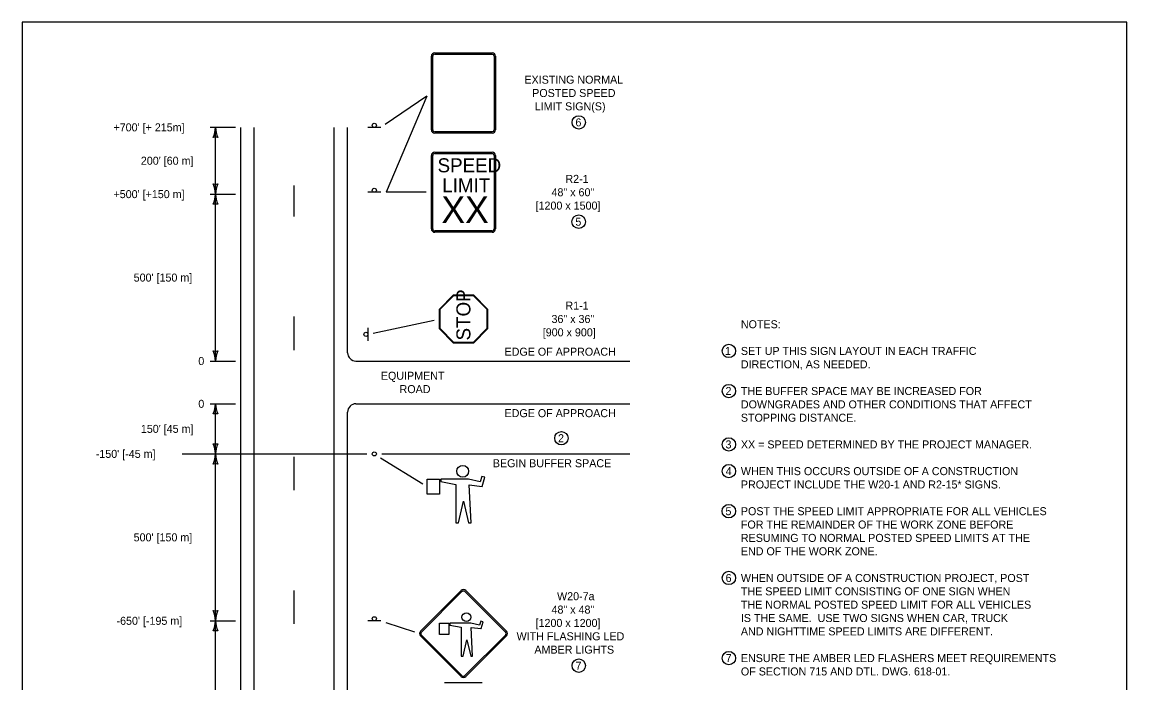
# Model space of a CAD drawing. Extents: x 49991.4 to 50021, y 49987.6 to 50011.4.
# Drawn here: x 50000.34 to 50008.61, y 50006.31 to 50011.26 of the extents above; entities that cross this region are included whole.
import ezdxf

# ---------------------------------------------------------------- set-up
doc = ezdxf.new("R2010")
doc.units = 0
for name, color, linetype in [('Level 1', 7, 'Continuous'), ('Level 2', 7, 'Continuous'), ('Level 3', 7, 'Continuous')]:
    doc.layers.add(name, color=color, linetype=linetype)

msp = doc.modelspace()

# ---------------------------------------------------------------- linework, layer by layer
at = {"layer": 'Level 1'}
for p, q in [((50003.4027, 50010.4569), (50003.4027, 50011.0069)), ((50003.4127, 50010.4569), (50003.4127, 50011.0069)), ((50003.4277, 50011.0319), (50003.8577, 50011.0319)), ((50003.4277, 50011.0219), (50003.8577, 50011.0219)), ((50003.8727, 50011.0069), (50003.8727, 50010.4569)), ((50003.8827, 50011.0069), (50003.8827, 50010.4569)), ((50001.9751, 50003.2038), (50001.9751, 50010.4747)), ((50002.0751, 50003.2038), (50002.0751, 50010.4747)), ((50002.6751, 50003.2038), (50002.6751, 50010.4747)), ((50002.775, 50008.7872), (50002.775, 50010.4747)), ((50003.023, 50010.4747), (50002.927, 50010.4747)), ((50003.8577, 50010.4419), (50003.4277, 50010.4419)), ((50003.8577, 50010.4319), (50003.4277, 50010.4319)), ((50003.4027, 50009.7137), (50003.4027, 50010.2637)), ((50003.4127, 50009.7137), (50003.4127, 50010.2637)), ((50003.4277, 50010.2887), (50003.8577, 50010.2887)), ((50003.4277, 50010.2787), (50003.8577, 50010.2787)), ((50003.8727, 50010.2637), (50003.8727, 50009.7137)), ((50003.8827, 50010.2637), (50003.8827, 50009.7137)), ((50002.375, 50009.8074), (50002.375, 50010.0394)), ((50003.023, 50009.9887), (50002.927, 50009.9887)), ((50003.8577, 50009.6987), (50003.4277, 50009.6987)), ((50003.8577, 50009.6887), (50003.4277, 50009.6887)), ((50002.375, 50008.8074), (50002.375, 50009.0574)), ((50002.927, 50008.9727), (50002.927, 50008.8767)), ((50002.8375, 50008.7247), (50004.89, 50008.7247)), ((50002.8375, 50008.4045), (50004.89, 50008.4045)), ((50002.7751, 50003.2038), (50002.7751, 50008.342)), ((50002.375, 50007.7574), (50002.375, 50008.0074)), ((50003.372, 50007.7285), (50003.372, 50007.841)), ((50003.372, 50007.841), (50003.4639, 50007.841)), ((50003.4639, 50007.841), (50003.4639, 50007.7285)), ((50003.6811, 50007.8403), (50003.4742, 50007.8403)), ((50003.4742, 50007.8403), (50003.4742, 50007.8217)), ((50003.4742, 50007.8217), (50003.5867, 50007.7995)), ((50003.7679, 50007.8203), (50003.6811, 50007.8403)), ((50003.7806, 50007.8599), (50003.7679, 50007.8203)), ((50003.8026, 50007.8544), (50003.7806, 50007.8599)), ((50003.7826, 50007.7856), (50003.8026, 50007.8544)), ((50003.4639, 50007.7285), (50003.372, 50007.7285)), ((50003.5867, 50007.7995), (50003.5867, 50007.5132)), ((50003.6998, 50007.5132), (50003.685, 50007.7966)), ((50003.685, 50007.7966), (50003.7826, 50007.7856)), ((50003.6049, 50007.5132), (50003.6432, 50007.6745)), ((50003.6432, 50007.6745), (50003.6815, 50007.5132)), ((50003.5867, 50007.5132), (50003.6049, 50007.5132)), ((50003.6815, 50007.5132), (50003.6998, 50007.5132)), ((50002.375, 50006.7574), (50002.375, 50007.0074)), ((50003.6249, 50007.0053), (50003.3208, 50006.7013)), ((50003.6319, 50006.9983), (50003.3279, 50006.6942)), ((50003.9572, 50006.6942), (50003.6532, 50006.9983)), ((50003.9643, 50006.7013), (50003.6602, 50007.0053)), ((50003.023, 50006.7795), (50002.927, 50006.7795)), ((50003.4642, 50006.6776), (50003.4642, 50006.7626)), ((50003.4642, 50006.7626), (50003.5337, 50006.7626)), ((50003.5337, 50006.7626), (50003.5337, 50006.6776)), ((50003.698, 50006.7622), (50003.5415, 50006.7622)), ((50003.5415, 50006.7622), (50003.5415, 50006.7481)), ((50003.5415, 50006.7481), (50003.6265, 50006.7313)), ((50003.7636, 50006.747), (50003.698, 50006.7622)), ((50003.7732, 50006.777), (50003.7636, 50006.747)), ((50003.7898, 50006.7728), (50003.7732, 50006.777)), ((50003.7747, 50006.7208), (50003.7898, 50006.7728)), ((50003.3208, 50006.6659), (50003.6249, 50006.3619)), ((50003.3279, 50006.673), (50003.6319, 50006.3689)), ((50003.5337, 50006.6776), (50003.4642, 50006.6776)), ((50003.6265, 50006.7313), (50003.6265, 50006.5148)), ((50003.6532, 50006.3689), (50003.9572, 50006.673)), ((50003.6602, 50006.3619), (50003.9643, 50006.6659)), ((50003.712, 50006.5148), (50003.7008, 50006.7291)), ((50003.7008, 50006.7291), (50003.7747, 50006.7208)), ((50003.6403, 50006.5148), (50003.6692, 50006.6368)), ((50003.6692, 50006.6368), (50003.6982, 50006.5148)), ((50003.6265, 50006.5148), (50003.6403, 50006.5148)), ((50003.6982, 50006.5148), (50003.712, 50006.5148)), ((50003.7839, 50006.3146), (50003.5016, 50006.3146))]:
    msp.add_line(p, q, dxfattribs=at)
for points in [[(50008.6146, 50011.2628), (50000.3356, 50011.2628), (50000.3356, 50000.0624), (50008.6146, 50000.0624)], [(50003.4627, 50008.9651), (50003.4627, 50009.1143), (50003.5682, 50009.2197), (50003.7172, 50009.2197), (50003.8227, 50009.1143), (50003.8227, 50008.9651), (50003.7172, 50008.8597), (50003.5682, 50008.8597)], [(50003.4677, 50008.9672), (50003.4677, 50009.1122), (50003.5702, 50009.2147), (50003.7152, 50009.2147), (50003.8177, 50009.1122), (50003.8177, 50008.9672), (50003.7152, 50008.8647), (50003.5702, 50008.8647)]]:
    msp.add_lwpolyline(points, close=True, dxfattribs=at)
for points in [[(50003.7805, 50007.8597), (50003.7807, 50007.8599)], [(50003.4635, 50007.7285), (50003.4639, 50007.7289)], [(50003.782, 50007.7857), (50003.7829, 50007.7868)], [(50003.7731, 50006.7768), (50003.7732, 50006.777)], [(50003.5334, 50006.6776), (50003.5337, 50006.6779)], [(50003.7742, 50006.7209), (50003.7749, 50006.7217)]]:
    msp.add_lwpolyline(points, dxfattribs=at)
for centre, radius in [((50002.975, 50010.49), 0.0152), ((50002.975, 50010.004), 0.0152), ((50002.9119, 50008.9247), 0.0152), ((50002.9751, 50008.0295), 0.0152), ((50003.6376, 50007.8991), 0.0442), ((50003.6652, 50006.8067), 0.0334), ((50002.975, 50006.7948), 0.0152)]:
    msp.add_circle(centre, radius, dxfattribs=at)
for centre, radius, start, end in [((50003.4277, 50011.007), 0.025, 90, 180), ((50003.4277, 50011.007), 0.015, 90, 180), ((50003.8577, 50011.007), 0.025, 0, 90), ((50003.8577, 50011.007), 0.015, 0, 90), ((50003.4277, 50010.457), 0.025, 180, 270), ((50003.4277, 50010.457), 0.015, 180, 270), ((50003.8577, 50010.457), 0.025, 270, 0), ((50003.8577, 50010.457), 0.015, 270, 0), ((50003.4277, 50010.2638), 0.025, 90, 180), ((50003.4277, 50010.2638), 0.015, 90, 180), ((50003.8577, 50010.2638), 0.025, 0, 90), ((50003.8577, 50010.2638), 0.015, 0, 90), ((50003.4277, 50009.7138), 0.025, 180, 270), ((50003.4277, 50009.7138), 0.015, 180, 270), ((50003.8577, 50009.7138), 0.025, 270, 0), ((50003.8577, 50009.7138), 0.015, 270, 0), ((50002.8376, 50008.7872), 0.0625, 180, 270), ((50002.8376, 50008.342), 0.0625, 90, 180), ((50003.6427, 50006.9877), 0.025, 45, 135), ((50003.6427, 50006.9877), 0.015, 45, 135), ((50003.3387, 50006.6837), 0.025, 135, 225), ((50003.3387, 50006.6837), 0.015, 135, 225), ((50003.9468, 50006.6837), 0.015, 315, 45.00024), ((50003.9468, 50006.6837), 0.025, 315, 45.00024), ((50003.6427, 50006.3796), 0.025, 225, 314.99957), ((50003.6427, 50006.3796), 0.015, 225, 314.99957)]:
    msp.add_arc(centre, radius, start, end, dxfattribs=at)
at = {"layer": 'Level 2'}
for centre, radius in [((50004.5068, 50010.5119), 0.05), ((50004.5066, 50009.768), 0.0507), ((50005.6319, 50008.8003), 0.05), ((50005.6319, 50008.5003), 0.05), ((50004.3766, 50008.147), 0.05), ((50005.6319, 50008.1003), 0.05), ((50005.6319, 50007.9003), 0.05), ((50005.6313, 50007.6003), 0.0507), ((50005.6319, 50007.1003), 0.05), ((50004.5068, 50006.4436), 0.05), ((50005.6319, 50006.5003), 0.05)]:
    msp.add_circle(centre, radius, dxfattribs=at)
at = {"layer": 'Level 3'}
for p, q in [((50003.3696, 50010.7094), (50003.0562, 50010.4971)), ((50003.3696, 50010.7094), (50003.063, 50009.9887)), ((50001.935, 50010.4747), (50001.745, 50010.4747)), ((50001.785, 50009.9747), (50001.785, 50010.4747)), ((50001.745, 50009.9747), (50001.935, 50009.9747)), ((50001.785, 50009.3497), (50001.785, 50009.9747)), ((50003.3627, 50009.9887), (50003.063, 50009.9887)), ((50001.785, 50008.7247), (50001.785, 50009.3497)), ((50002.9662, 50008.9344), (50003.4236, 50009.0314)), ((50001.745, 50008.7247), (50001.935, 50008.7247)), ((50001.745, 50008.4045), (50001.935, 50008.4045)), ((50001.785, 50008.0295), (50001.785, 50008.4045)), ((50001.5358, 50008.0295), (50002.9198, 50008.0295)), ((50001.7851, 50007.1842), (50001.7851, 50008.0295)), ((50003.0217, 50008.0007), (50003.338, 50007.8057)), ((50003.0221, 50008.0005), (50003.338, 50007.8057)), ((50003.0303, 50008.0295), (50004.89, 50008.0295)), ((50001.7851, 50006.7795), (50001.7851, 50007.1842)), ((50001.745, 50006.7795), (50001.9351, 50006.7795)), ((50001.7851, 50005.2795), (50001.7851, 50006.7795)), ((50003.061, 50006.767), (50003.2757, 50006.6962))]:
    msp.add_line(p, q, dxfattribs=at)
for centre, radius, start, end in [((50001.5629, 50010.4838), 0.2223, 337.45601, 357.63952), ((50001.5629, 50010.4838), 0.2223, 337.45601, 357.63952), ((50002.0177, 50010.4862), 0.233, 182.82731, 202.07716), ((50002.0177, 50010.4862), 0.233, 182.82731, 202.07716), ((50001.785, 50010.3465), 0.0548, 72.13882, 107.86118), ((50001.785, 50010.3465), 0.0548, 72.13882, 107.86118), ((50001.785, 50010.1029), 0.0548, 252.13882, 287.86118), ((50001.5523, 50009.9632), 0.233, 2.82731, 22.07716), ((50002.0072, 50009.9655), 0.2223, 157.45601, 177.63952), ((50001.5629, 50009.9838), 0.2223, 337.45601, 357.63952), ((50002.0177, 50009.9862), 0.233, 182.82731, 202.07716), ((50001.785, 50009.8465), 0.0548, 72.13882, 107.86118), ((50001.785, 50008.8529), 0.0548, 252.13882, 287.86118), ((50001.5523, 50008.7132), 0.233, 2.82731, 22.07716), ((50002.0072, 50008.7155), 0.2223, 157.45601, 177.63952), ((50001.5629, 50008.4136), 0.2223, 337.45601, 357.63952), ((50002.0177, 50008.416), 0.233, 182.82731, 202.07716), ((50001.785, 50008.2763), 0.0548, 72.13882, 107.86118), ((50001.785, 50008.1577), 0.0548, 252.13882, 287.86118), ((50001.5523, 50008.018), 0.233, 2.82731, 22.07716), ((50002.0072, 50008.0203), 0.2223, 157.45601, 177.63952), ((50001.5629, 50008.0386), 0.2223, 337.45601, 357.63952), ((50002.0178, 50008.041), 0.233, 182.82731, 202.07716), ((50001.7851, 50007.9013), 0.0548, 72.13882, 107.86118), ((50001.7851, 50006.9077), 0.0548, 252.13882, 287.86118), ((50001.5524, 50006.768), 0.233, 2.82731, 22.07716), ((50002.0072, 50006.7703), 0.2223, 157.45601, 177.63952), ((50001.5629, 50006.7886), 0.2223, 337.45601, 357.63952), ((50002.0178, 50006.791), 0.233, 182.82731, 202.07716), ((50001.7851, 50006.6513), 0.0548, 72.13882, 107.86118)]:
    msp.add_arc(centre, radius, start, end, dxfattribs=at)

# ---------------------------------------------------------------- texts
at = {"layer": 'Level 1'}
for s, height, p in [('SPEED', 0.10512, (50003.449, 50010.1379)), ('LIMIT', 0.10512, (50003.4844, 50009.9878)), ('XX', 0.19892, (50003.4778, 50009.7583))]:
    msp.add_text(s, height=height, dxfattribs=at).set_placement(p)
msp.add_text('STOP', height=0.10512, rotation=90, dxfattribs=at).set_placement((50003.6952, 50008.8789))
at = {"layer": 'Level 2'}
for s, p in [('EXISTING NORMAL', (50004.0998, 50010.8019)), ('POSTED SPEED', (50004.158, 50010.7019)), ('LIMIT SIGN(S)', (50004.1773, 50010.6019)), ('6', (50004.4822, 50010.4819)), ("+700' [+ 215m]", (50001.0204, 50010.4447)), ("200' [60 m]", (50001.2255, 50010.1947)), ('R2-1', (50004.407, 50010.0587)), ("+500' [+150 m]", (50001.0204, 50009.9447)), ('48" x 60"', (50004.3029, 50009.9587)), ('[1200 x 1500]', (50004.1834, 50009.8587)), ('5', (50004.4817, 50009.738)), ("500' [150 m]", (50001.1717, 50009.3197)), ('R1-1', (50004.407, 50009.1097)), ('36" x 36"', (50004.3029, 50009.0097)), ('[900 x 900]', (50004.2373, 50008.9097)), ('NOTES:', (50005.7219, 50008.9703)), ('EDGE OF APPROACH', (50003.9508, 50008.7647)), ('1', (50005.6026, 50008.7703)), ('SET UP THIS SIGN LAYOUT IN EACH TRAFFIC ', (50005.7219, 50008.7703)), ('0', (50001.6562, 50008.6947)), ('DIRECTION, AS NEEDED.', (50005.7219, 50008.6703)), ('EQUIPMENT', (50003.0239, 50008.5846)), ('ROAD', (50003.1642, 50008.4846)), ('2', (50005.6068, 50008.4703)), ('THE BUFFER SPACE MAY BE INCREASED FOR', (50005.7219, 50008.4703)), ('0', (50001.6562, 50008.3745)), ('DOWNGRADES AND OTHER CONDITIONS THAT AFFECT ', (50005.7219, 50008.3703)), ('EDGE OF APPROACH', (50003.9508, 50008.3045)), ('STOPPING DISTANCE.', (50005.7219, 50008.2703)), ("150' [45 m]", (50001.2255, 50008.187)), ('2', (50004.3515, 50008.117)), ("-150' [-45 m]", (50000.8877, 50007.9995)), ('3', (50005.6067, 50008.0703)), ('XX = SPEED DETERMINED BY THE PROJECT MANAGER.', (50005.7219, 50008.0703)), ('BEGIN BUFFER SPACE', (50003.8632, 50007.9295)), ('4', (50005.608, 50007.8703)), ('WHEN THIS OCCURS OUTSIDE OF A CONSTRUCTION ', (50005.7219, 50007.8703)), ('PROJECT INCLUDE THE W20-1 AND R2-15* SIGNS.', (50005.7219, 50007.7703)), ('5', (50005.6063, 50007.5703)), ('POST THE SPEED LIMIT APPROPRIATE FOR ALL VEHICLES ', (50005.7219, 50007.5703)), ('FOR THE REMAINDER OF THE WORK ZONE BEFORE ', (50005.7219, 50007.4703)), ("500' [150 m]", (50001.1716, 50007.3745)), ('RESUMING TO NORMAL POSTED SPEED LIMITS AT THE ', (50005.7219, 50007.3703)), ('END OF THE WORK ZONE.', (50005.7219, 50007.2703)), ('6', (50005.6074, 50007.0703)), ('WHEN OUTSIDE OF A CONSTRUCTION PROJECT, POST ', (50005.7219, 50007.0703)), ('W20-7a', (50004.3444, 50006.9336)), ('THE SPEED LIMIT CONSISTING OF ONE SIGN WHEN ', (50005.7219, 50006.9703)), ('THE NORMAL POSTED SPEED LIMIT FOR ALL VEHICLES ', (50005.7219, 50006.8703)), ('48" x 48"', (50004.303, 50006.8336)), ('IS THE SAME.  USE TWO SIGNS WHEN CAR, TRUCK ', (50005.7219, 50006.7703)), ("-650' [-195 m]", (50001.0431, 50006.7495)), ('[1200 x 1200]', (50004.1835, 50006.7336)), ('WITH FLASHING LED', (50004.0413, 50006.6336)), ('AND NIGHTTIME SPEED LIMITS ARE DIFFERENT.', (50005.7219, 50006.6703)), ('AMBER LIGHTS', (50004.1745, 50006.5336)), ('7', (50005.6081, 50006.4703)), ('ENSURE THE AMBER LED FLASHERS MEET REQUIREMENTS', (50005.7219, 50006.4703)), ('7', (50004.483, 50006.4136)), ('OF SECTION 715 AND DTL. DWG. 618-01.', (50005.7219, 50006.3703))]:
    msp.add_text(s, height=0.06, dxfattribs=at).set_placement(p)

doc.saveas('drawing.dxf')
